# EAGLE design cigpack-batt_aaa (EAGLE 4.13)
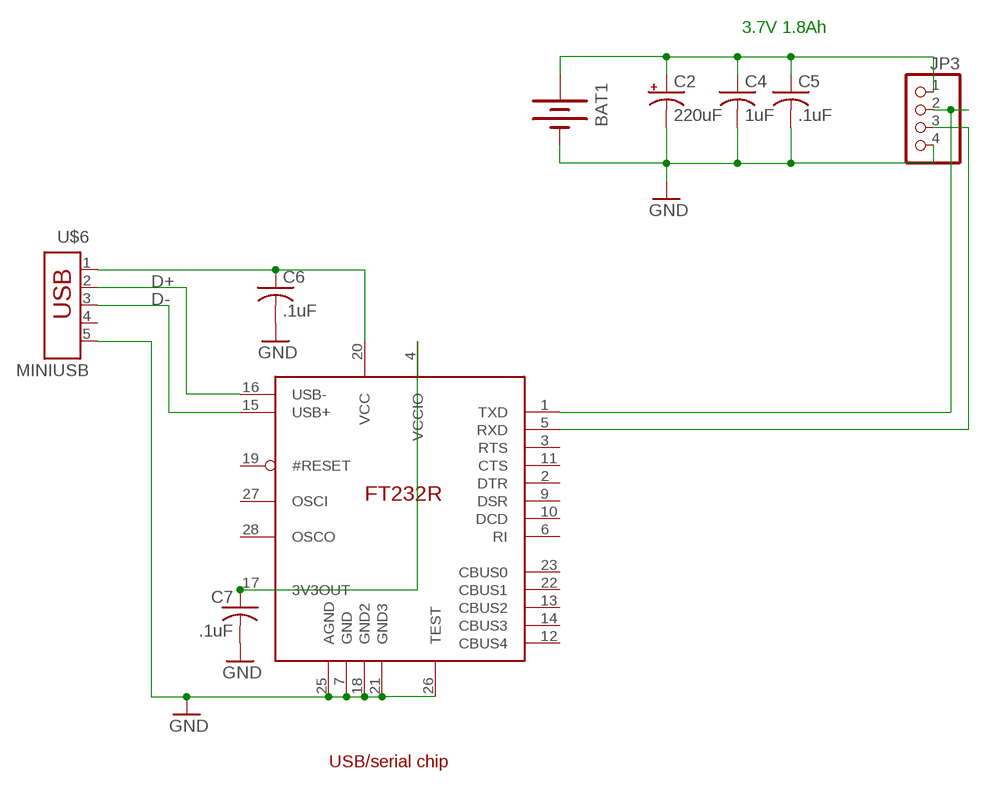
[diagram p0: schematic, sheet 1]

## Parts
BAT1  BATTERYAAA  [3AAA-PC]
C2  220uF  CPOL-US153CLV-0810  [153CLV-0810]
C4  1uF  C-USC3225  [C3225]
C5  .1uF  C-USC1206  [C1206]
C6  .1uF  C-USC1206  [C1206]
C7  .1uF  C-USC1206  [C1206]
IC2  FT232R  [TSSOP28]
JP3  PINHD-1X4  [1X04]
U$6  MINIUSB  [UX60A-MB-5SY]

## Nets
D+: IC2.16(USB-) U$6.2
D-: IC2.15(USB+) U$6.3
GND: BAT1.- C2.- C4.2 C5.2 C6.2 C7.2 IC2.7(GND) IC2.18(GND2) IC2.21(GND3) IC2.25(AGND) IC2.26(TEST) JP3.4 U$6.5
N$1: IC2.1(TXD) JP3.2
N$8: BAT1.+ C2.+ C4.1 C5.1 JP3.1
N$11: C6.1 IC2.20(VCC) U$6.1
N$17: C7.1 IC2.4(VCCIO) IC2.17(3V3OUT)
N$41: IC2.5(RXD) JP3.3
Unconnected: IC2.2(DTR) IC2.3(RTS) IC2.6(RI) IC2.9(DSR) IC2.10(DCD) IC2.11(CTS) IC2.12(CBUS4) IC2.13(CBUS2) IC2.14(CBUS3) IC2.19(#RESET) IC2.22(CBUS1) IC2.23(CBUS0) IC2.27(OSCI) IC2.28(OSCO) U$6.4

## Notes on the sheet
- 3.7V 1.8Ah
- USB/serial chip

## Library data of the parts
BAT1 = cleanair:BATTERY: BATTERY
C2 = rcl:CPOL-US: POLARIZED CAPACITOR, American symbol
C4-C7 = rcl:C-US: CAPACITOR, American symbol
IC2 = ft232:FT232R
JP3 = pinhead:PINHD-1X4: PIN HEADER
U$6 = cleanair:MINIUSB

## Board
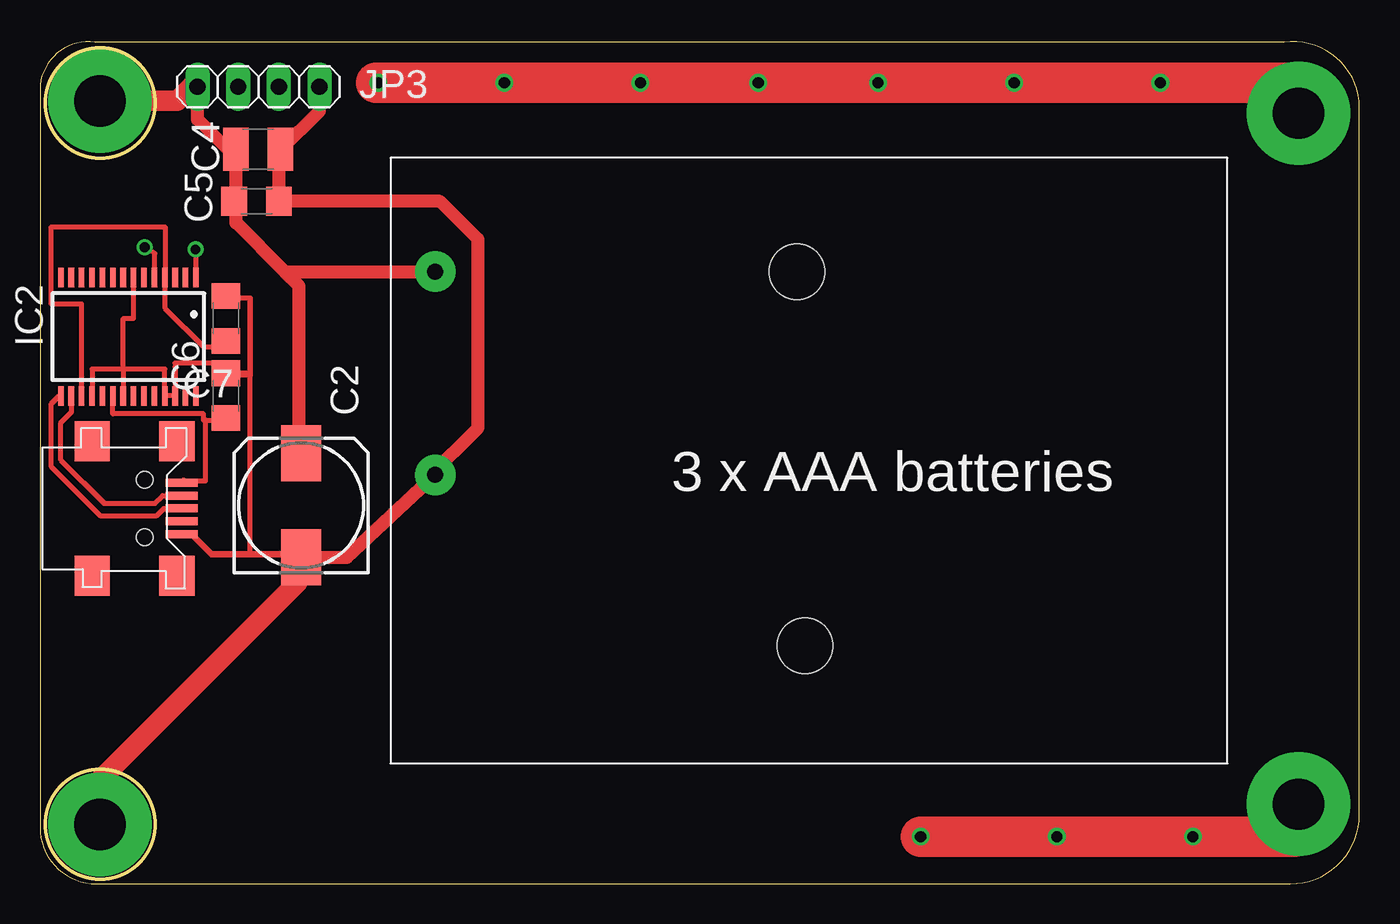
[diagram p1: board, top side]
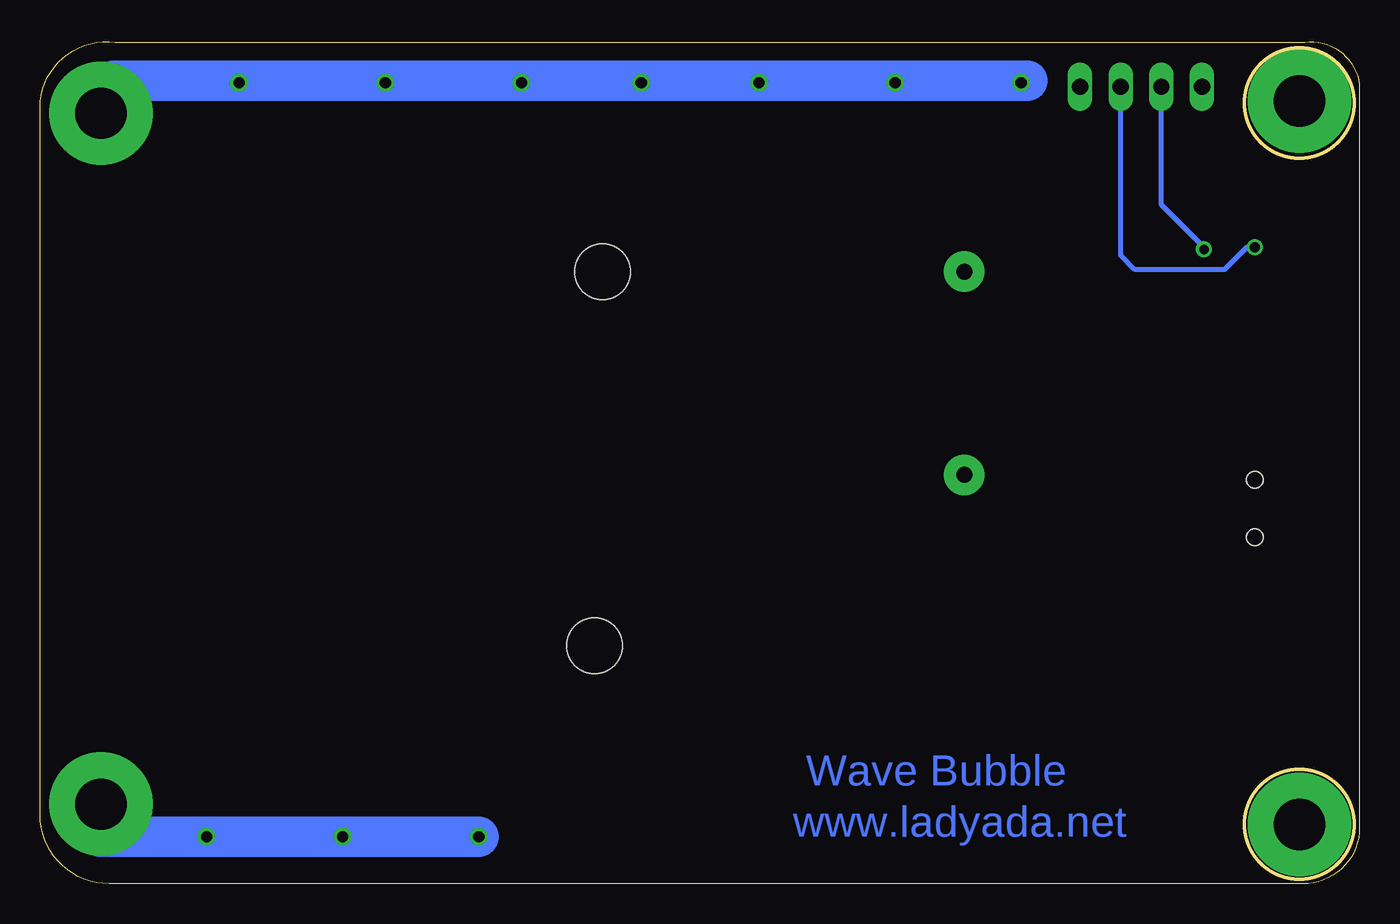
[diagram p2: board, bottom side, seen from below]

Size 82.49 x 52.63 mm. Coordinates in mm from the lower left corner, seen from the top.
Outline: 3.43,52.6 arc90 0,49.93 0,3.52 arc90 3.52,0 78.16,0 arc90 82.49,4.33 82.49,48.9 arc90 77.78,52.6 3.43,52.6
Outline: circle at 3.75,3.71 radius 3.43
Outline: circle at 3.75,48.79 radius 3.43
Copper layers (1*16): Top 0.035mm / dielectric 1.5mm / Bottom 0.035mm
Design rules "default": minimum track width 12mil, minimum drill 23mil, track to track 10mil, track to pad 10mil, pad to pad 10mil, via to via 10mil, smd to smd 1mil, copper to edge 20mil, drill to drill 8mil, minimum pad ring 10mil, minimum via ring 8mil, stop-mask expansion 4mil, vias tented up to drill 0mil, thermal gap 10mil

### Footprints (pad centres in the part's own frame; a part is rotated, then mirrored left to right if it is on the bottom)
3AAA-PC = drill 1 pad 2.54 round: + 23.368,-11.938; - 23.368,0.762 | hole 3.454: 0.762,-11.938; 0.254,11.43
153CLV-0810 = smd 3.5 x 2.5: + 3.25,0; - -3.25,0
C3225 = smd 1.6 x 2.7: 1 -1.4,0; 2 1.4,0
C1206 = smd 1.6 x 1.8: 1 -1.4,0; 2 1.4,0
TSSOP28 = smd 0.35 x 1.2: 1 -4.225,-3.7; 2 -3.575,-3.7; 3 -2.925,-3.7; 4 -2.275,-3.7; 5 -1.625,-3.7; 6 -0.975,-3.7; 7 -0.325,-3.7; 8 0.325,-3.7; 9 0.975,-3.7; 10 1.625,-3.7; 11 2.275,-3.7; 12 2.925,-3.7; 13 3.575,-3.7; 14 4.225,-3.7; 15 4.225,3.7; 16 3.575,3.7; 17 2.925,3.7; 18 2.275,3.7; 19 1.625,3.7; 20 0.975,3.7; 21 0.325,3.7; 22 -0.325,3.7; 23 -0.975,3.7; 24 -1.625,3.7; 25 -2.275,3.7; 26 -2.925,3.7; 27 -3.575,3.7; 28 -4.225,3.7
1X04 = drill 1.016 long: 1 -3.81,0; 2 -1.27,0; 3 1.27,0; 4 3.81,0
UX60A-MB-5SY = smd 0.5 x 2: 1 -1.6,2.3; 2 -0.8,2.3; 3 0,2.3; 4 0.8,2.3; 5 1.6,2.3 | smd 2.5 x 2.2: C1 -4.2,2; C2 -4.2,-3.3; C3 4.2,-3.3; C4 4.2,2 | hole 1.016: -1.8,0; 1.8,0

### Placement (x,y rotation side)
BAT1  48.08,26.31 180 top
C2  16.32,23.65 90 top
C4  13.64,45.89 0 top
C5  13.54,42.65 0 top
C6  11.63,30.5 90 top
C7  11.63,35.33 90 top
IC2  5.53,34.19 180 top
JP3  13.66,49.81 0 top
U$6  6.56,23.46 270 top

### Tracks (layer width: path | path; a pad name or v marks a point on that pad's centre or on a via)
19GHZANT  (via drill 0.7, 3.2 pad 6.45)
  Top 0.305: 78.68,3.83 78.81,3.96 | 78.68,3.83 78.55,3.83 78.43,2.95 | v78.68,4.98 78.68,3.83
  Top 2.54: v55.06,2.95 59.12,2.95 v63.57,2.95 67.76,2.95 v72.08,2.95 78.43,2.95
  Bottom 2.54: v55.06,2.95 59.12,2.95 v63.57,2.95 67.76,2.95 v72.08,2.95 78.68,2.95 v78.68,4.98
800MHZANT  (via drill 0.7, 3.2 pad 6.45)
  Top 0.305: 78.81,50.06 79.44,49.43 v78.68,48.16
  Top 0.406: 73.6,50.19 73.35,50.44 72.97,50.06
  Top 2.54: 21.02,50.06 v21.15,50.06 v29.02,50.06 v37.53,50.06 41.98,50.06 | 42.36,50.06 v52.39,50.06 v60.9,50.06 v70.05,50.06 72.97,50.06 78.81,50.06 | 41.98,50.06 v44.9,50.06 42.36,50.06 | 41.98,50.06 42.36,50.06
  Bottom 2.54: v78.68,48.16 78.68,49.81 77.92,50.19 20.77,50.19
D+
  Top 0.305: U$6.2 7.67,24.26 7.18,23.77 4.01,23.77 1.3,26.48 1.3,28.82 1.97,29.49 1.97,30.5 IC2.16
D-
  Top 0.305: U$6.3 7.75,23.46 7.31,23.01 3.75,23.01 0.7,26.06 0.7,30 1.21,30.5 1.23,30.49 IC2.15
GND  (via drill 3.2 pad 6.45)
  Top 0.305: 13.15,36.6 13.15,31.9 | C7.2 11.75,36.6 13.15,36.6 | 13.15,31.9 C6.2 12.01,31.77 13.15,31.77 13.15,31.9 | 7.94,30.49 IC2.25 7.81,32.16 5.15,32.16 | 7.94,30.49 IC2.26 8.46,32.29 8.45,32.29 | 7.94,30.49 7.94,30.5 | 5.21,32.16 IC2.21 | 5.21,32.16 5.21,35.33 5.86,35.33 IC2.7 | IC2.18 3.26,32.16 5.15,32.16 | 5.15,32.16 5.21,32.16 | 8.45,32.29 8.45,32.28 | 10.99,32.54 8.45,32.54 8.45,32.29 | 13.15,20.6 13.15,36.6
  Top 0.406: U$6.5 8.87,21.87 9.47,21.87 10.74,20.6 13.15,20.6 16.12,20.6 C2.- | C6.2 10.99,32.54
  Top 0.813: JP3.4 17.47,48.29 15.05,45.87 C4.2 15.04,45.6 14.93,45.49 14.94,45.48 C5.2 25.01,42.65 27.37,40.28 27.37,28.47 24.33,25.43 BAT1.- 19.17,20.4 C2.-
  Top 1.27: v3.75,3.71 3.75,6.5 16.07,18.82 16.07,20.22 16.25,20.4 C2.-
N$1  (via drill 0.6)
  Top 0.305: IC2.1 9.76,38.85 v9.72,39.65
  Bottom 0.305: v9.72,39.65 9.72,39.78 12.39,42.44 JP3.2
N$8  (via drill 3.2 pad 6.45)
  Top 0.813: JP3.1 9.85,47.78 11.75,45.87 11.78,45.89 C4.1 12.26,45.87 12.26,42.7 12.19,42.7 C5.1 12.14,42.31 12.26,42.19 12.26,41.3 15.31,38.25 | 15.31,38.25 BAT1.+ | C2.+ 16.25,26.82 16.2,26.82 16.2,37.36 15.31,38.25
  Top 1.27: JP3.1 9.47,49.81 8.58,48.92 v3.75,48.92
N$11
  Top 0.305: IC2.20 4.56,29.36 10.23,29.36 10.23,28.98 10.36,28.98 | C6.1 12,28.98 10.36,28.98 | 8.97,25.17 10.36,25.17 10.36,28.98
  Top 0.406: U$6.1 8.97,25.17
N$17
  Top 0.305: C7.1 11.75,33.55 10.23,33.55 7.81,35.98 IC2.4 7.81,38.24 7.82,38.25 7.82,41.05 0.7,41.05 0.7,36.22 2.6,36.22 IC2.17
N$41  (via drill 0.6)
  Top 0.305: IC2.5 7.16,37.89 7.18,39.4 v6.55,39.78
  Bottom 0.305: v6.55,39.78 7.05,39.78 8.45,38.38 14.04,38.38 14.93,39.27 JP3.3

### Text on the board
Bottom: Wave Bubble | www.ladyada.net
